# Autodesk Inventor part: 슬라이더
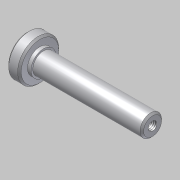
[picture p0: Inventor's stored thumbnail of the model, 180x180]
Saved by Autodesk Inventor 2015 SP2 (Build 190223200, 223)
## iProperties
Created: 2011-04
Part Number: 슬라이더
Document SubType Name: Modeling
Designer: 한국산업디자인학원 [http://gmhk.co.kr]
Density: 1 g/cm^3
Material: 일반
Appearance: 기본값
Author: pww
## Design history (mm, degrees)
sketch "스케치1"
  geometry: L1 (-7, 0)-(63, 0); L2 (63, 0)-(63, 6); L3 (63, 6)-(0, 6); L4 (-7, 0)-(-7, 11.5); L5 (-7, 11.5)-(0, 11.5); L6 (0, 11.5)-(0, 6); 1 further point
  constraints: 12 end point, 3 perpendicular, 2 horizontal, 2 point on line, 1 parallel
  dimensions: "d1" = 70 distance of L1.start L1.end; "d19" = 12 diameter of L3 L1; "d20" = 7 distance of L4.end L5.end; "d21" = 23 diameter of L5 L1
revolve "회전1" stored, may be unused: angle "d4" = 90 deg
chamfer "모따기1" distance "d16" = 1; stored, may be unused: second distance "d17" = 2, angle "d18" = 45 deg
hole "구멍2" diameter "d24" = 4.917; stored, may be unused: countersink angle "d28" = 90 deg, drill point angle "d30" = 118 deg; dims "d22" = 10, "d23" = 10, "d25" = 10, "d26" = 4, "d27" = 2, "d29" = 13
sketch "스케치2"
  geometry: C1 r 7 at (0, 0); 1 further point
  constraints: 1 centre point, 1 coincident
  dimensions: "d31" = 14 diameter of C1
extrude "돌출2" join sketch "스케치2" distance "d32" = 2; taper "d33" = 0 deg
node "솔리드1"
